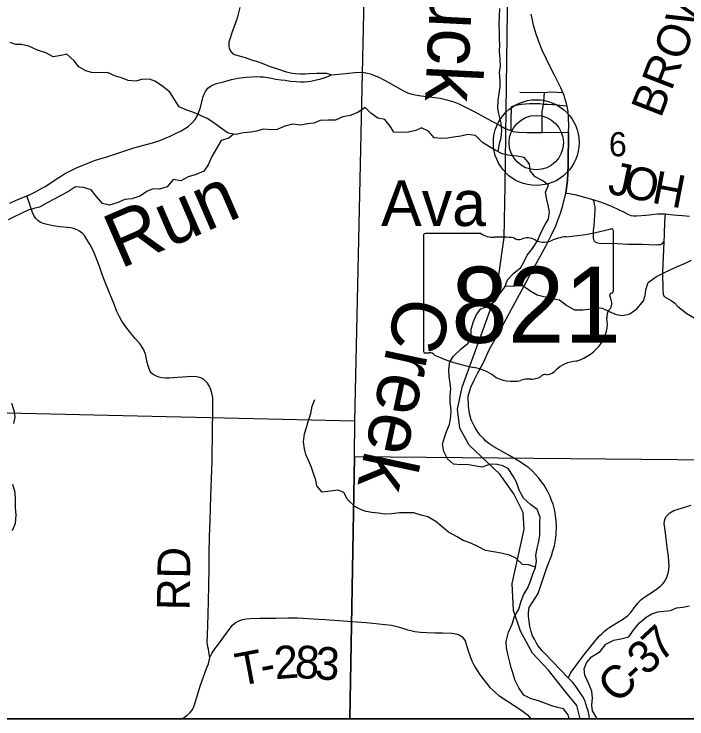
# Model space of a CAD drawing. Extents: x 0 to 34, y 0 to 22.
# Drawn here: x 4.145 to 5.312, y 14.573 to 15.796 of the extents above; entities that cross this region are included whole.
import ezdxf

# ---------------------------------------------------------------- set-up
doc = ezdxf.new("R2010")
doc.units = 0
for name, color, linetype in [('GM_X_Corporation', 7, 'Continuous'), ('GM_X_County_Road', 7, 'Continuous'), ('GM_X_County_Road_Text', 7, 'Continuous'), ('GM_X_Minor_River', 7, 'Continuous'), ('GM_X_Minor_River_Text', 7, 'Continuous'), ('GM_X_Rail_Line', 7, 'Continuous'), ('GM_X_Section_Text', 7, 'Continuous'), ('GM_X_State_Location', 7, 'Continuous'), ('GM_X_State_Route', 7, 'Continuous'), ('GM_X_State_Shield', 7, 'Continuous'), ('GM_X_Township_Road', 7, 'Continuous'), ('GM_X_Township_Road_Text', 7, 'Continuous'), ('GM_X_Unincorporated', 7, 'Continuous'), ('GM_X_Unincorporated_Location', 7, 'Continuous'), ('GM_X_Unincorporated_Text', 7, 'Continuous'), ('SH_Text', 7, 'Continuous')]:
    doc.layers.add(name, color=color, linetype=linetype)

msp = doc.modelspace()

# ---------------------------------------------------------------- linework, layer by layer
at = {"layer": 'GM_X_Corporation'}
for points in [[(1.6311, 14.5734), (8.4311, 14.5734), (8.4311, 20.028)], [(3.7221, 14.5734), (8.4311, 14.5734)]]:
    msp.add_lwpolyline(points, dxfattribs=at)
for points in [[(4.7583, 16.0869), (5.7783, 16.0638), (5.82, 16.0635), (5.7937, 15.0184), (4.7356, 15.0283), (4.7361, 15.0901)], [(3.7181, 14.5734), (4.7275, 14.5734), (4.7356, 15.0283), (4.7361, 15.0901), (3.7309, 15.1133)], [(4.7275, 14.5734), (5.7869, 14.5734), (5.7937, 15.0184), (4.7356, 15.0283)]]:
    msp.add_lwpolyline(points, close=True, dxfattribs=at)
at = {"layer": 'GM_X_County_Road'}
for points in [[(4.1377, 15.4684), (4.1474, 15.4727), (4.167, 15.4807), (4.1741, 15.484), (4.182, 15.4878), (4.1903, 15.4922), (4.1988, 15.4973), (4.2068, 15.5025), (4.2181, 15.51), (4.2256, 15.5147), (4.2325, 15.5188), (4.2439, 15.5248), (4.2533, 15.5292), (4.2634, 15.5337), (4.2748, 15.5384), (4.2846, 15.542), (4.294, 15.545), (4.3023, 15.5474), (4.3143, 15.5513), (4.3337, 15.5579), (4.3525, 15.564), (4.3698, 15.5686), (4.3853, 15.573), (4.3976, 15.5771), (4.409, 15.5816), (4.4157, 15.5846), (4.4226, 15.5877), (4.4351, 15.5939), (4.4407, 15.5973), (4.4469, 15.6013), (4.4533, 15.6067), (4.4591, 15.6133), (4.463, 15.6202), (4.4656, 15.6265), (4.4683, 15.6343), (4.4716, 15.6484), (4.4731, 15.653), (4.4748, 15.6572), (4.477, 15.6619), (4.4813, 15.6678), (4.4868, 15.6719), (4.4913, 15.6741), (4.4963, 15.6759), (4.5085, 15.6789), (4.5223, 15.6825), (4.5332, 15.6848), (4.5476, 15.6867), (4.5579, 15.6876), (4.5656, 15.6877), (4.5717, 15.6875), (4.5779, 15.6871), (4.5916, 15.6848), (4.599, 15.6835), (4.6077, 15.6822), (4.6154, 15.6813), (4.6247, 15.6801), (4.634, 15.6793), (4.6419, 15.6786), (4.6489, 15.6785), (4.6545, 15.6791), (4.6598, 15.6801), (4.6664, 15.6814), (4.6745, 15.6834), (4.6809, 15.6853), (4.6862, 15.6869), (4.6953, 15.6911), (4.7021, 15.6916), (4.7141, 15.6927), (4.725, 15.6937), (4.7358, 15.6947), (4.7456, 15.6954), (4.7524, 15.6949), (4.7583, 15.6937), (4.7632, 15.6923), (4.7685, 15.6903), (4.773, 15.6887), (4.7774, 15.6867), (4.795, 15.6776), (4.8141, 15.6666), (4.8207, 15.6628), (4.8272, 15.6598), (4.8331, 15.6581), (4.8405, 15.6564), (4.8512, 15.6545), (4.8653, 15.6526), (4.8843, 15.6501), (4.8957, 15.6477), (4.9075, 15.6441), (4.9163, 15.6403), (4.9302, 15.6337), (4.9441, 15.6265), (4.961, 15.6173), (4.9739, 15.6102), (4.9879, 15.6027), (4.9969, 15.5979), (5.0064, 15.5942), (5.0105, 15.5928), (5.015, 15.5919), (5.021, 15.5915), (5.0347, 15.5909), (5.0609, 15.591), (5.1067, 15.5916)], [(5.1067, 15.5916), (5.1062, 15.5343), (5.1048, 15.5073), (5.1025, 15.4901), (5.1021, 15.4858)], [(5.1021, 15.4858), (5.1079, 15.4852), (5.1178, 15.4831), (5.1487, 15.4743), (5.16, 15.4711), (5.1699, 15.4676), (5.1824, 15.4623), (5.1924, 15.4579), (5.203, 15.4523), (5.2086, 15.4494), (5.2147, 15.447), (5.2192, 15.4463), (5.2251, 15.4464), (5.2405, 15.4475), (5.2511, 15.4485), (5.2612, 15.4496), (5.2742, 15.4498), (5.2797, 15.4491), (5.2881, 15.4481), (5.2955, 15.4473), (5.3042, 15.4465), (5.3163, 15.4458)], [(5.1061, 14.6447), (5.1114, 14.6547), (5.1329, 14.6835), (5.1532, 14.7093), (5.1603, 14.7173), (5.1642, 14.7212), (5.1687, 14.7253), (5.1733, 14.7291), (5.1785, 14.7327), (5.1903, 14.7401), (5.2004, 14.7461), (5.2087, 14.7522), (5.2147, 14.7579), (5.2221, 14.7684), (5.2268, 14.774), (5.2317, 14.7792), (5.2375, 14.7843), (5.2567, 14.7967), (5.2661, 14.8038), (5.269, 14.8068), (5.2724, 14.8107), (5.2749, 14.8146), (5.277, 14.8186), (5.2784, 14.8226), (5.2798, 14.8285), (5.2807, 14.8328), (5.2812, 14.839), (5.2809, 14.8463), (5.28, 14.8557), (5.2779, 14.8706), (5.2748, 14.896), (5.2724, 14.9123), (5.2735, 14.9197), (5.2768, 14.9252), (5.2822, 14.9309), (5.2893, 14.9349), (5.3194, 14.944)]]:
    msp.add_lwpolyline(points, dxfattribs=at)
at = {"layer": 'GM_X_Minor_River'}
for points in [[(4.9844, 15.5574), (4.9871, 15.5718), (4.9898, 15.5816), (4.9912, 15.5941), (4.9901, 15.607), (4.9862, 15.6207), (4.9839, 15.6324), (4.9846, 15.6468), (4.9865, 15.6582), (4.9884, 15.6707), (4.988, 15.6802), (4.9868, 15.6957), (4.9886, 15.7052), (4.9882, 15.7181), (4.9867, 15.7318), (4.9874, 15.7428), (4.987, 15.7534), (4.987, 15.7636), (4.9865, 15.778), (4.9869, 15.7928), (4.9876, 15.8061)], [(4.6758, 15.6116), (4.6648, 15.6067), (4.6538, 15.6059), (4.6425, 15.6036), (4.6281, 15.605), (4.6145, 15.6016), (4.6012, 15.5958), (4.5914, 15.5954), (4.577, 15.5965), (4.5657, 15.5931), (4.5558, 15.5915), (4.543, 15.5903), (4.5297, 15.5873), (4.5165, 15.5899), (4.5009, 15.6008), (4.4914, 15.6076), (4.48, 15.6148), (4.4683, 15.6204), (4.455, 15.6261), (4.4444, 15.6298), (4.4315, 15.6351), (4.4231, 15.6479), (4.4151, 15.6608), (4.4022, 15.671), (4.3893, 15.6801), (4.3799, 15.6834), (4.3662, 15.683), (4.3564, 15.6799), (4.3431, 15.681), (4.3333, 15.6852), (4.3212, 15.6885), (4.3071, 15.6949), (4.292, 15.6941), (4.2795, 15.6948), (4.2696, 15.6975), (4.2575, 15.705), (4.2495, 15.7152), (4.2366, 15.7269), (4.2268, 15.7242), (4.2131, 15.7219), (4.2003, 15.7291), (4.1859, 15.7336), (4.1707, 15.7403), (4.1578, 15.7437), (4.148, 15.7437), (4.1385, 15.7467)], [(5.0454, 14.8261), (5.0492, 14.8363), (5.0511, 14.847), (5.0499, 14.8568), (5.0525, 14.8694), (5.0547, 14.8788), (5.057, 14.8914), (5.0569, 14.9141), (5.0576, 14.9236), (5.0523, 14.9369), (5.0405, 14.9455), (5.0288, 14.9561), (5.0211, 14.9705), (5.0166, 14.9841), (5.0108, 14.9944), (5.0021, 15.0076), (4.9926, 15.0125), (4.9831, 15.0147), (4.9706, 15.0151), (4.957, 15.0101), (4.943, 15.0127), (4.9301, 15.0149), (4.9192, 15.0141), (4.907, 15.0156), (4.8968, 15.0247), (4.8903, 15.0376), (4.888, 15.0501), (4.8918, 15.0618), (4.8951, 15.0721), (4.9, 15.0842), (4.9026, 15.0979), (4.903, 15.1093), (4.9014, 15.1225), (4.9014, 15.135), (4.9025, 15.146), (4.9013, 15.1559), (4.8994, 15.1673), (4.8993, 15.1798), (4.9008, 15.1931), (4.9072, 15.2026), (4.9204, 15.2155), (4.9325, 15.2254), (4.9378, 15.2383), (4.9381, 15.2493), (4.9419, 15.2626), (4.9471, 15.2751), (4.9547, 15.285), (4.9672, 15.2896), (4.98, 15.2995), (4.9868, 15.3101), (4.9962, 15.3223), (5.0011, 15.3352), (5.0117, 15.347), (5.0241, 15.3565), (5.0294, 15.366), (5.0351, 15.3778), (5.0441, 15.3896), (5.0528, 15.4029), (5.0595, 15.4181), (5.0663, 15.431), (5.072, 15.4405), (5.0735, 15.4534), (5.0711, 15.4648), (5.0688, 15.4746), (5.0669, 15.4871), (5.0718, 15.4993), (5.0623, 15.5072), (5.0487, 15.514), (5.0403, 15.5242), (5.0391, 15.5367), (5.0296, 15.5476), (5.0175, 15.5499), (5.005, 15.551), (4.9917, 15.5536), (4.9792, 15.56), (4.9697, 15.566), (4.9572, 15.5736), (4.9451, 15.5853), (4.9318, 15.5871), (4.9201, 15.5844), (4.9072, 15.5829), (4.897, 15.5809), (4.8868, 15.5801), (4.8739, 15.5816), (4.864, 15.593), (4.8519, 15.5986), (4.8421, 15.5944), (4.8292, 15.5913), (4.8178, 15.5905), (4.8038, 15.5916), (4.7974, 15.6018), (4.7882, 15.6132), (4.7757, 15.6158), (4.764, 15.6241), (4.7537, 15.6339), (4.7413, 15.6255), (4.728, 15.6205), (4.7155, 15.6178), (4.7023, 15.6121), (4.6894, 15.6124), (4.6758, 15.6116)], [(4.5254, 15.5881), (4.5176, 15.5808), (4.504, 15.5769), (4.4961, 15.5629), (4.4882, 15.5492), (4.4814, 15.5348), (4.4739, 15.5238), (4.461, 15.518), (4.447, 15.5138), (4.4342, 15.5069), (4.4209, 15.5092), (4.4107, 15.4966), (4.3971, 15.4924), (4.3865, 15.4931), (4.3763, 15.4889), (4.3634, 15.4805), (4.3491, 15.4759), (4.3369, 15.4748), (4.3237, 15.469), (4.3105, 15.4648), (4.2983, 15.4678), (4.2877, 15.4799), (4.2786, 15.4912), (4.2653, 15.4954), (4.2517, 15.4965), (4.2396, 15.4885), (4.226, 15.4812), (4.2158, 15.4755), (4.2025, 15.4686), (4.1893, 15.461), (4.1795, 15.4591), (4.1693, 15.456), (4.1572, 15.4503), (4.1454, 15.4445), (4.1349, 15.4392)], [(4.9969, 15.324), (5.0136, 15.325), (5.0276, 15.3251), (5.0413, 15.3156), (5.0523, 15.3092), (5.0781, 15.3025), (5.0909, 15.3003), (5.1039, 15.2904), (5.1171, 15.2833), (5.1315, 15.2833), (5.1417, 15.2845), (5.1519, 15.2868), (5.1648, 15.2861), (5.1758, 15.2808), (5.1891, 15.2748), (5.2008, 15.2733), (5.2129, 15.276), (5.2258, 15.2856), (5.2367, 15.2985), (5.2397, 15.308), (5.2405, 15.3178), (5.245, 15.3304), (5.2593, 15.3407), (5.2699, 15.346), (5.2839, 15.3529), (5.2967, 15.3586), (5.3081, 15.3636), (5.3202, 15.3693)], [(5.0493, 14.8369), (5.0371, 14.8409), (5.0268, 14.8412), (5.0151, 14.8522), (5.0044, 14.8574), (4.99, 14.8608), (4.9768, 14.8634), (4.9628, 14.8656), (4.9503, 14.8717), (4.937, 14.8784), (4.9241, 14.8829), (4.9135, 14.8894), (4.8983, 14.8973), (4.8881, 14.9063), (4.8767, 14.9158), (4.8626, 14.9241), (4.8513, 14.9271), (4.8384, 14.9308), (4.8134, 14.9307), (4.7998, 14.9292), (4.7869, 14.9287), (4.777, 14.9302), (4.7653, 14.9313), (4.7558, 14.9332), (4.7456, 14.9366), (4.7361, 14.9418), (4.7232, 14.9543), (4.7167, 14.966), (4.7073, 14.9702), (4.6936, 14.9686), (4.6796, 14.9667), (4.6701, 14.9776), (4.6682, 14.9875), (4.6651, 14.9977), (4.6609, 15.0095), (4.6567, 15.0193), (4.651, 15.0322), (4.6487, 15.0417), (4.6468, 15.0542), (4.6486, 15.0682), (4.652, 15.0788), (4.655, 15.0891), (4.6599, 15.1031), (4.6621, 15.116), (4.6666, 15.1278)], [(4.1404, 15.1211), (4.1453, 15.1067), (4.1465, 15.0968), (4.1439, 15.0858)], [(4.1423, 14.9804), (4.1461, 14.9668), (4.1469, 14.9531), (4.147, 14.9398), (4.1478, 14.9273), (4.1467, 14.9125), (4.1418, 14.8996)], [(5.1078, 14.5734), (5.106, 14.5802), (5.098, 14.5911), (5.0874, 14.5934), (5.0779, 14.596), (5.0685, 14.5998), (5.0548, 14.6046), (5.0419, 14.608), (5.029, 14.6148), (5.0203, 14.6273), (5.0138, 14.6409), (5.0108, 14.6515), (5.0073, 14.6618), (5.0046, 14.672), (5.0012, 14.686), (4.9989, 14.6966), (4.9988, 14.7076), (5.0026, 14.7239), (5.009, 14.738), (5.0127, 14.7513), (5.0206, 14.7638), (5.0248, 14.7779), (5.0293, 14.7896), (5.0357, 14.7999), (5.0406, 14.8124), (5.0454, 14.8261)], [(5.1572, 14.5734), (5.1556, 14.5747), (5.148, 14.5875), (5.1472, 14.5974), (5.1483, 14.6095), (5.1472, 14.6217), (5.1411, 14.6353), (5.135, 14.6493), (5.1338, 14.6603), (5.1379, 14.6705), (5.1466, 14.6812), (5.1613, 14.6903), (5.1715, 14.7029), (5.1851, 14.7098), (5.1976, 14.7121), (5.2112, 14.7159), (5.2207, 14.7292), (5.2297, 14.7403), (5.2414, 14.7498), (5.2512, 14.7555), (5.2615, 14.759), (5.2721, 14.7605), (5.2838, 14.7617), (5.294, 14.7659), (5.305, 14.7671), (5.3167, 14.7694)]]:
    msp.add_lwpolyline(points, dxfattribs=at)
at = {"layer": 'GM_X_Rail_Line'}
msp.add_lwpolyline([(5.1268, 14.5734), (5.121, 14.5964), (5.1018, 14.62), (5.072, 14.6581), (5.044, 14.6874), (5.0233, 14.7257), (5.0114, 14.7615), (5.0087, 14.8086), (5.0196, 14.8552), (5.0298, 14.9025), (5.0281, 14.9315), (5.0121, 14.9641), (4.9877, 14.9978), (4.9344, 15.0485), (4.9183, 15.0781), (4.9141, 15.111), (4.9221, 15.149), (4.9771, 15.2997), (4.9859, 15.3434), (4.995, 15.4085), (4.997, 15.4988), (5.0024, 15.9327)], dxfattribs=at)
at = {"layer": 'GM_X_State_Route'}
for points in [[(5.1067, 15.5916), (5.107, 15.601), (5.1068, 15.616), (5.1061, 15.627), (5.1046, 15.6362), (5.1031, 15.6412), (5.1005, 15.6506), (5.099, 15.6547), (5.0966, 15.6604), (5.0931, 15.6684), (5.0823, 15.6902), (5.0753, 15.7038), (5.0682, 15.7181), (5.0605, 15.7347), (5.0568, 15.7439), (5.0506, 15.7615), (5.0467, 15.7749), (5.0418, 15.7963)], [(5.1021, 15.4858), (5.1025, 15.4901), (5.1048, 15.5073), (5.1062, 15.5343), (5.1067, 15.5916)], [(5.0844, 15.4286), (5.0861, 15.4322), (5.0929, 15.4506), (5.0968, 15.4639), (5.1021, 15.4858)], [(5.143, 14.5734), (5.1424, 14.5793), (5.1409, 14.5874), (5.1386, 14.5939), (5.1369, 14.5996), (5.1347, 14.6051), (5.1308, 14.6128), (5.1259, 14.6206), (5.12, 14.6288), (5.114, 14.6365), (5.1061, 14.6447), (5.0655, 14.6869), (5.0612, 14.6915), (5.057, 14.6966), (5.0537, 14.701), (5.0506, 14.7061), (5.0474, 14.7116), (5.0443, 14.7177), (5.0417, 14.7249), (5.0393, 14.7342), (5.0382, 14.7423), (5.0373, 14.7517), (5.0374, 14.758), (5.0383, 14.7664), (5.054, 14.7911), (5.0684, 14.8345), (5.0772, 14.8564), (5.0797, 14.865), (5.0824, 14.8739), (5.084, 14.8838), (5.0854, 14.8933), (5.0859, 14.9082), (5.0855, 14.9169), (5.0843, 14.9258), (5.0829, 14.9343), (5.0799, 14.9459), (5.0773, 14.9526), (5.0748, 14.9592), (5.0703, 14.9686), (5.0642, 14.9788), (5.0598, 14.9849), (5.0551, 14.9912), (5.0495, 14.9977), (5.0437, 15.0035), (5.0376, 15.0088), (5.0311, 15.0137), (5.0254, 15.0177), (5.0161, 15.0235), (5.0049, 15.0298), (4.9864, 15.04), (4.9772, 15.0453), (4.9682, 15.0513), (4.9634, 15.0554), (4.9595, 15.0592), (4.9534, 15.0659), (4.9499, 15.0704), (4.9442, 15.0794), (4.9379, 15.0925), (4.935, 15.1035), (4.933, 15.1161), (4.9329, 15.1334), (4.9375, 15.149), (4.9428, 15.1612), (4.95, 15.1752), (4.9585, 15.1906), (4.9696, 15.2146), (4.9902, 15.252), (5.0078, 15.2843), (5.0286, 15.3227), (5.0429, 15.3495), (5.0673, 15.3935), (5.0768, 15.4121), (5.0844, 15.4286)]]:
    msp.add_lwpolyline(points, dxfattribs=at)
at = {"layer": 'GM_X_State_Shield'}
for p, q in [((5.1844, 15.3156), (5.1844, 15.4203)), ((4.8549, 15.4119), (4.8549, 15.2118)), ((4.9546, 15.4153), (4.8581, 15.4153)), ((5.1844, 15.3156), (5.1844, 15.3156))]:
    msp.add_line(p, q, dxfattribs=at)
for centre, major_axis, start_param, end_param in [((5.067, 15.6882), (0.3495, 0), 4.814394, 5.042369), ((5.1808, 15.4207), (0.00367, 0), 6.141152, 7.989035), ((4.8586, 15.4123), (0.00382, 0), 1.712693, 3.28349), ((4.9776, 15.4386), (0.037, 0), 4.042523, 4.731795), ((4.9899, 15.303), (0.133, 0), 1.404758, 1.657858), ((5.0201, 15.4134), (0.0107, 0), 3.836095, 5.185415), ((5.0358, 15.3902), (0.0222, 0), 0.950623, 2.079405), ((5.1116, 15.3542), (0.0703, 0), 1.699011, 2.107814), ((5.0644, 15.4219), (0.0267, 0), 4.081561, 5.145723), ((5.1836, 15.3079), (0.00568, 0), 1.883978, 3.671073), ((5.1805, 15.3152), (0.00393, 0), 5.05454, 6.418171), ((5.1475, 15.2947), (0.0341, 0), 5.934695, 6.695948), ((5.1976, 15.2718), (0.0248, 0), 2.387724, 3.262537), ((5.0866, 15.2585), (0.0874, 0), 5.101752, 6.440018), ((4.8587, 15.2113), (0.00385, 0), 3.00124, 4.508301), ((4.8593, 15.2318), (0.0294, 0), 4.665946, 4.897461), ((4.8653, 15.2002), (0.0106, 0), 0.519207, 1.627899), ((4.9991, 15.38), (0.2524, 0), 4.195997, 4.488961), ((5.1235, 15.1556), (0.0479, 0), 1.647645, 2.488434), ((4.9238, 15.1219), (0.079, 0), 0.823519, 1.323587), ((5.0628, 15.1924), (0.0282, 0), 4.937069, 5.64225), ((5.0093, 15.1992), (0.0501, 0), 4.026481, 4.996735), ((5.0382, 15.13), (0.0412, 0), 1.495662, 1.94098), ((5.0419, 15.1842), (0.0267, 0), 4.691044, 5.507374), ((5.066, 15.1649), (0.00752, 0), 1.147584, 2.315152)]:
    msp.add_ellipse(centre, major_axis=major_axis, ratio=0.8, start_param=start_param, end_param=end_param, dxfattribs=at)
at = {"layer": 'GM_X_Township_Road'}
for points in [[(4.5367, 15.8078), (4.5323, 15.7913), (4.5306, 15.7856), (4.5225, 15.7636), (4.5197, 15.7547), (4.5177, 15.7475), (4.5175, 15.7409), (4.5183, 15.7363), (4.5211, 15.7314), (4.5247, 15.7274), (4.5292, 15.7253), (4.5456, 15.7208), (4.5571, 15.717), (4.5664, 15.714), (4.5763, 15.7104), (4.5877, 15.706), (4.6072, 15.6993), (4.6152, 15.6967), (4.6246, 15.6942), (4.6329, 15.6931), (4.6419, 15.6926), (4.6497, 15.6925), (4.657, 15.6929), (4.6699, 15.6936), (4.6867, 15.6935), (4.6908, 15.6926), (4.6953, 15.6911)], [(5.0221, 15.6605), (5.0648, 15.6603), (5.0754, 15.6611), (5.0865, 15.6608), (5.0966, 15.6604)], [(5.0631, 15.6394), (5.064, 15.645), (5.0648, 15.6603)], [(5.1046, 15.6362), (5.0915, 15.6374), (5.0795, 15.6388), (5.0709, 15.6396), (5.0631, 15.6394), (5.057, 15.6403), (5.051, 15.6405), (5.0389, 15.6403), (5.0249, 15.6393), (5.015, 15.6377), (5.0072, 15.6356), (5.0068, 15.6105), (5.0064, 15.5942)], [(5.0609, 15.591), (5.0608, 15.6175), (5.0611, 15.6274), (5.0631, 15.6394)], [(4.4362, 14.5734), (4.4401, 14.576), (4.4451, 14.5798), (4.4504, 14.5846), (4.4528, 14.5875), (4.455, 14.5904), (4.4588, 14.5995), (4.4617, 14.6091), (4.4684, 14.632), (4.4789, 14.661), (4.482, 14.6692), (4.4846, 14.6797), (4.4829, 14.6897), (4.482, 14.6943), (4.4803, 14.7006), (4.4802, 14.7077), (4.4803, 14.7188), (4.4818, 14.7544), (4.4827, 14.8032), (4.4836, 14.8373), (4.4834, 14.8609), (4.484, 14.8892), (4.485, 14.9183), (4.4855, 14.9392), (4.4865, 14.9599), (4.4884, 15.0203), (4.4893, 15.077), (4.49, 15.1046), (4.49, 15.1155), (4.4895, 15.1308), (4.4883, 15.1383), (4.4859, 15.1459), (4.4834, 15.1512), (4.4803, 15.156), (4.4743, 15.1622), (4.4688, 15.1651), (4.462, 15.1669), (4.4535, 15.1675), (4.4452, 15.167), (4.4287, 15.1655), (4.4147, 15.1644), (4.4077, 15.1646), (4.4015, 15.1653), (4.3962, 15.1664), (4.3911, 15.1685), (4.3864, 15.1711), (4.3833, 15.1733), (4.3811, 15.176), (4.3791, 15.1806), (4.3775, 15.1858), (4.376, 15.192), (4.3729, 15.2061), (4.3715, 15.2101), (4.3699, 15.214), (4.3641, 15.2227), (4.3557, 15.2329), (4.3471, 15.2433), (4.3373, 15.2558), (4.3317, 15.2634), (4.3276, 15.2709), (4.3229, 15.2813), (4.3184, 15.2927), (4.3099, 15.3139), (4.3019, 15.3339), (4.2979, 15.3447), (4.293, 15.3585), (4.2865, 15.3765), (4.282, 15.3861), (4.2762, 15.3969), (4.2714, 15.4052), (4.2673, 15.4118), (4.2631, 15.416), (4.2582, 15.4198), (4.2542, 15.422), (4.2482, 15.424), (4.2434, 15.4252), (4.2377, 15.426), (4.2242, 15.4274), (4.213, 15.4288), (4.2022, 15.431), (4.1955, 15.433), (4.1902, 15.4351), (4.1861, 15.438), (4.1825, 15.4413), (4.1797, 15.4457), (4.1773, 15.4511), (4.1746, 15.4585), (4.1709, 15.4694), (4.167, 15.4807)], [(5.1487, 15.4743), (5.1504, 15.4707), (5.1512, 15.4662), (5.1521, 15.4618), (5.1524, 15.4552), (5.1516, 15.4475), (5.1503, 15.4287), (5.1494, 15.4205), (5.1492, 15.4127), (5.1494, 15.4082), (5.15, 15.405), (5.1514, 15.4026), (5.1534, 15.4008), (5.1553, 15.3999), (5.1601, 15.399), (5.1919, 15.3981), (5.2095, 15.3973), (5.2344, 15.3973), (5.2588, 15.3961), (5.263, 15.3963), (5.2661, 15.3966), (5.2691, 15.3979), (5.2721, 15.4013)], [(5.2742, 15.4498), (5.2734, 15.4362), (5.2725, 15.4136), (5.2721, 15.4013)], [(5.2721, 15.4013), (5.2694, 15.3487), (5.27, 15.3176), (5.2707, 15.3101), (5.2726, 15.3062), (5.2845, 15.2993), (5.2905, 15.2952), (5.2964, 15.2891), (5.3119, 15.2766), (5.3245, 15.2691)], [(4.4846, 14.6797), (4.4879, 14.6869), (4.4914, 14.6929), (4.4993, 14.7029), (4.5182, 14.7284), (4.5239, 14.7363), (4.5283, 14.7401), (4.5349, 14.7437), (4.5381, 14.7449), (4.5416, 14.7457), (4.5473, 14.7469), (4.555, 14.7474), (4.5715, 14.7479), (4.5989, 14.748), (4.6197, 14.7489), (4.6366, 14.7485), (4.6736, 14.7464), (4.6848, 14.7456), (4.7235, 14.7429), (4.7558, 14.7409), (4.7996, 14.7363), (4.8133, 14.7325), (4.8257, 14.7287), (4.8401, 14.725), (4.8498, 14.7237), (4.8611, 14.7232), (4.8746, 14.7229), (4.8886, 14.7228), (4.9048, 14.722), (4.9138, 14.7204), (4.9184, 14.7186), (4.9221, 14.7158), (4.9248, 14.7127), (4.9272, 14.7089), (4.929, 14.7031), (4.9319, 14.6931), (4.9361, 14.6816), (4.939, 14.6739), (4.9422, 14.6673), (4.9452, 14.662), (4.9522, 14.6512), (4.9595, 14.6409), (4.9704, 14.6281), (4.9858, 14.6141), (5.0256, 14.5878), (5.0354, 14.5802), (5.0392, 14.5766), (5.0412, 14.5736), (5.0413, 14.5734)]]:
    msp.add_lwpolyline(points, dxfattribs=at)
at = {"layer": 'GM_X_Unincorporated'}
for radius in [0.0744, 0.0472]:
    msp.add_circle((5.0507, 15.5732), radius, dxfattribs=at)
at = {"layer": 'GM_X_Unincorporated_Location'}
msp.add_line((5.0507, 15.5732), (5.0507, 15.5732), dxfattribs=at)
at = {"layer": 'SH_Text'}
msp.add_line((8.4311, 14.5734), (1.6311, 14.5734), dxfattribs=at)

# ---------------------------------------------------------------- texts
at = {"layer": 'GM_X_County_Road_Text'}
for s, rotation, p in [('J', 347.9868, (5.1729, 15.4855)), ('O', 348.003, (5.199, 15.4799)), ('H', 349.0764, (5.2491, 15.4693)), ('7', 42.9021, (5.2666, 14.6704)), ('3', 43.5721, (5.2414, 14.6464)), ('C', 44.1389, (5.1912, 14.5978)), ('-', 43.9788, (5.2247, 14.6303))]:
    msp.add_text(s, height=0.0568, rotation=rotation, dxfattribs=at).set_placement(p)
at = {"layer": 'GM_X_Minor_River_Text'}
for s, height, rotation, p in [('Duck', 0.0947, 267.1501, (4.8721, 15.9346)), ('Run', 0.09469, 23.4688, (4.3294, 15.3538)), ('Creek', 0.09471, 257.9571, (4.811, 15.3103))]:
    msp.add_text(s, height=height, rotation=rotation, dxfattribs=at).set_placement(p)
at = {"layer": 'GM_X_Section_Text'}
msp.add_text('6', height=0.0419, rotation=0, dxfattribs=at).set_placement((5.1766, 15.5495))
at = {"layer": 'GM_X_State_Location'}
for s, p in [('s', (5.016, 15.2985)), ('r', (5.0159, 15.2985))]:
    msp.add_text(s, height=0.000189, dxfattribs=at).set_placement(p)
msp.add_text('821', height=0.000189, rotation=0, dxfattribs=at).set_placement((4.9491, 15.2847))
at = {"layer": 'GM_X_State_Shield'}
msp.add_text('821', height=0.13184, dxfattribs=at).set_placement((4.9034, 15.2259))
at = {"layer": 'GM_X_Township_Road_Text'}
for s, height, rotation, p in [('BROWN', 0.05682, 68.739, (5.2667, 15.6144)), ('RD', 0.05682, 89.0128, (4.4493, 14.7615)), ('2', 0.0568, 4.4227, (4.598, 14.6421)), ('8', 0.0568, 356.4227, (4.6308, 14.6448)), ('3', 0.0568, 356.2295, (4.6657, 14.6426)), ('T', 0.0568, 10.751, (4.535, 14.6301)), ('-', 0.0568, 10.6225, (4.5767, 14.638))]:
    msp.add_text(s, height=height, rotation=rotation, dxfattribs=at).set_placement(p)
at = {"layer": 'GM_X_Unincorporated_Text'}
msp.add_text('Ava', height=0.07898, rotation=0, dxfattribs=at).set_placement((4.7816, 15.4286))

doc.saveas('drawing.dxf')
